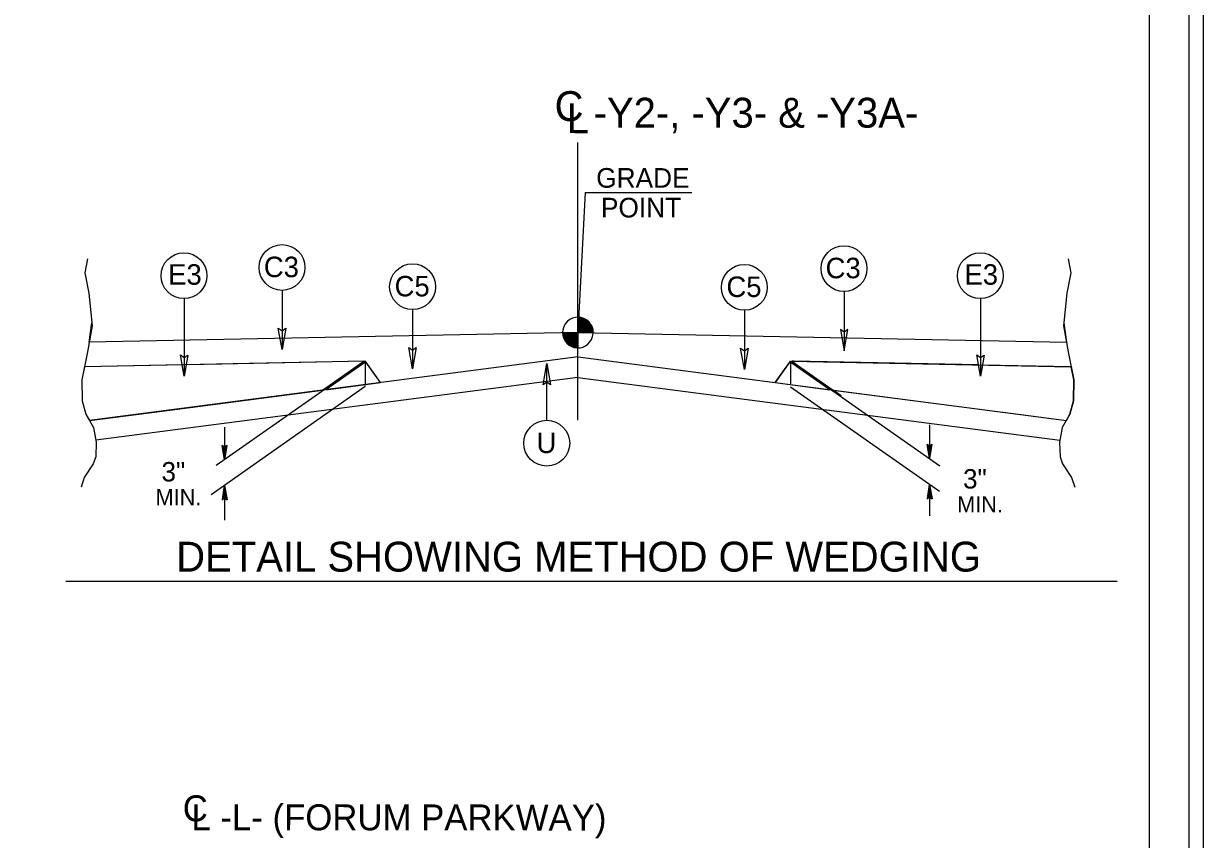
# Model space of a CAD drawing. Extents: x 1904401 to 1905163, y 193929 to 194736.
# Drawn here: x 1904973 to 1905047.5, y 194555.3 to 194606.9 of the extents above; entities that cross this region are included whole.
import ezdxf

# ---------------------------------------------------------------- set-up
doc = ezdxf.new("R2010")
doc.units = 0
for name, color, linetype in [('Old_Level_1', 7, 'Continuous'), ('Old_Level_11', 7, 'Continuous'), ('Old_Level_2', 7, 'Continuous'), ('Old_Level_20', 7, 'Continuous'), ('Old_Level_21', 7, 'Continuous'), ('Old_Level_3', 7, 'Continuous'), ('Prop Shade Medium', 7, 'Continuous'), ('Sheet Plot Border Inside CELL', 7, 'Continuous'), ('Sheet Plot Border Outside CELL', 7, 'Continuous'), ('Sheet Typical CELL', 7, 'Continuous'), ('Typical Text Centerline CELL', 7, 'Continuous')]:
    doc.layers.add(name, color=color, linetype=linetype)

msp = doc.modelspace()

# ---------------------------------------------------------------- linework, layer by layer
at = {"layer": 'Old_Level_1'}
for p, q in [((1905007.984, 194581.801), (1905007.984, 194599.347)), ((1905007.984, 194587.34), (1905007.984, 194588.305)), ((1905007.017, 194587.34), (1905007.984, 194587.34)), ((1905007.978, 194586.373), (1905007.978, 194587.329)), ((1905007.984, 194587.34), (1905007.984, 194586.373)), ((1905008.952, 194587.34), (1905007.984, 194587.34)), ((1905007.984, 194586.373), (1905007.984, 194587.34)), ((1904994.56, 194585.532), (1904976.825, 194585.177)), ((1904994.56, 194585.532), (1904985.144, 194578.938)), ((1904995.525, 194584.177), (1904994.56, 194585.532)), ((1904994.56, 194585.532), (1904994.56, 194583.985)), ((1905020.446, 194584.18), (1905021.408, 194585.532)), ((1905021.408, 194585.532), (1905039.145, 194585.177)), ((1905021.408, 194585.532), (1905021.408, 194584.094)), ((1905021.409, 194585.532), (1905030.84, 194578.928)), ((1904994.553, 194583.937), (1904984.818, 194577.085)), ((1905021.408, 194583.907), (1905030.824, 194577.311)), ((1904985.674, 194581.358), (1904985.674, 194579.307)), ((1905030.202, 194581.508), (1905030.202, 194579.375)), ((1904985.674, 194579.307), (1904985.513, 194580.21)), ((1904985.674, 194580.094), (1904985.513, 194580.21)), ((1904985.674, 194579.307), (1904985.536, 194580.194)), ((1904985.561, 194580.176), (1904985.674, 194579.307)), ((1904985.674, 194579.307), (1904985.584, 194580.16)), ((1904985.606, 194580.144), (1904985.674, 194579.307)), ((1904985.674, 194579.307), (1904985.628, 194580.128)), ((1904985.651, 194580.111), (1904985.674, 194579.307)), ((1904985.674, 194579.307), (1904985.833, 194580.21)), ((1904985.833, 194580.21), (1904985.674, 194580.094)), ((1904985.81, 194580.194), (1904985.674, 194579.307)), ((1904985.674, 194579.307), (1904985.788, 194580.176)), ((1904985.765, 194580.16), (1904985.674, 194579.307)), ((1904985.674, 194579.307), (1904985.741, 194580.144)), ((1904985.72, 194580.128), (1904985.674, 194579.307)), ((1904985.674, 194579.307), (1904985.697, 194580.111)), ((1904985.674, 194580.094), (1904985.674, 194579.307)), ((1905030.202, 194579.375), (1905030.043, 194580.277)), ((1905030.202, 194580.16), (1905030.043, 194580.277)), ((1905030.202, 194579.375), (1905030.066, 194580.26)), ((1905030.088, 194580.244), (1905030.202, 194579.375)), ((1905030.202, 194579.375), (1905030.11, 194580.228)), ((1905030.133, 194580.21), (1905030.202, 194579.375)), ((1905030.202, 194579.375), (1905030.156, 194580.194)), ((1905030.178, 194580.176), (1905030.202, 194579.375)), ((1905030.202, 194579.375), (1905030.36, 194580.277)), ((1905030.36, 194580.277), (1905030.202, 194580.16)), ((1905030.337, 194580.26), (1905030.202, 194579.375)), ((1905030.202, 194579.375), (1905030.315, 194580.244)), ((1905030.292, 194580.228), (1905030.202, 194579.375)), ((1905030.202, 194579.375), (1905030.269, 194580.21)), ((1905030.247, 194580.194), (1905030.202, 194579.375)), ((1905030.202, 194579.375), (1905030.224, 194580.176)), ((1905030.202, 194580.16), (1905030.202, 194579.375)), ((1904985.674, 194577.686), (1904985.513, 194576.783)), ((1904985.538, 194576.8), (1904985.674, 194577.686)), ((1904985.674, 194577.686), (1904985.561, 194576.817)), ((1904985.584, 194576.833), (1904985.674, 194577.686)), ((1904985.674, 194577.686), (1904985.606, 194576.85)), ((1904985.628, 194576.866), (1904985.674, 194577.686)), ((1904985.674, 194577.686), (1904985.651, 194576.883)), ((1904985.674, 194577.686), (1904985.674, 194575.492)), ((1904985.674, 194577.686), (1904985.833, 194576.783)), ((1904985.674, 194576.9), (1904985.674, 194577.686)), ((1904985.697, 194576.883), (1904985.674, 194577.686)), ((1904985.674, 194577.686), (1904985.72, 194576.866)), ((1904985.743, 194576.85), (1904985.674, 194577.686)), ((1904985.674, 194577.686), (1904985.765, 194576.833)), ((1904985.788, 194576.817), (1904985.674, 194577.686)), ((1904985.674, 194577.686), (1904985.81, 194576.8)), ((1905030.202, 194577.748), (1905030.043, 194576.846)), ((1905030.066, 194576.863), (1905030.202, 194577.748)), ((1905030.202, 194577.748), (1905030.088, 194576.88)), ((1905030.11, 194576.897), (1905030.202, 194577.748)), ((1905030.202, 194577.748), (1905030.133, 194576.914)), ((1905030.156, 194576.931), (1905030.202, 194577.748)), ((1905030.202, 194577.748), (1905030.178, 194576.946)), ((1905030.202, 194577.748), (1905030.202, 194575.768)), ((1905030.202, 194577.748), (1905030.36, 194576.846)), ((1905030.202, 194576.965), (1905030.202, 194577.748)), ((1905030.224, 194576.946), (1905030.202, 194577.748)), ((1905030.202, 194577.748), (1905030.247, 194576.931)), ((1905030.269, 194576.914), (1905030.202, 194577.748)), ((1905030.202, 194577.748), (1905030.292, 194576.897)), ((1905030.315, 194576.88), (1905030.202, 194577.748)), ((1905030.202, 194577.748), (1905030.337, 194576.863)), ((1904985.513, 194576.783), (1904985.674, 194576.9)), ((1904985.674, 194576.9), (1904985.833, 194576.783)), ((1905030.043, 194576.846), (1905030.202, 194576.965)), ((1905030.202, 194576.965), (1905030.36, 194576.846))]:
    msp.add_line(p, q, dxfattribs=at)
for points in [[(1904977.013, 194592.005), (1904976.85, 194591.106), (1904977.096, 194589.828), (1904977.312, 194587.76), (1904977.013, 194586.126), (1904976.66, 194584.357), (1904976.687, 194583.023), (1904976.905, 194582.18), (1904977.396, 194581.335), (1904977.558, 194580.41), (1904977.531, 194579.485), (1904977.368, 194579.048), (1904976.797, 194578.177), (1904976.606, 194577.578)], [(1905038.956, 194592.005), (1905039.119, 194591.106), (1905038.874, 194589.828), (1905038.657, 194587.76), (1905038.956, 194586.126), (1905039.31, 194584.357), (1905039.283, 194583.023), (1905039.064, 194582.18), (1905038.574, 194581.335), (1905038.412, 194580.41), (1905038.438, 194579.485), (1905038.602, 194579.048), (1905039.172, 194578.177), (1905039.363, 194577.578)], [(1905007.993, 194588.305), (1905007.993, 194588.305), (1905007.993, 194587.34)], [(1905008.012, 194588.305), (1905008.012, 194587.34)], [(1905008.032, 194588.305), (1905008.032, 194587.34)], [(1905008.051, 194588.304), (1905008.051, 194587.34)], [(1905008.072, 194588.303), (1905008.072, 194587.34)], [(1905008.09, 194588.3), (1905008.09, 194587.34)], [(1905008.11, 194588.299), (1905008.11, 194587.34)], [(1905008.128, 194588.295), (1905008.128, 194587.34)], [(1905008.148, 194588.292), (1905008.148, 194587.34)], [(1905008.167, 194588.288), (1905008.167, 194587.34)], [(1905008.187, 194588.286), (1905008.187, 194587.34)], [(1905008.207, 194588.281), (1905008.207, 194587.34)], [(1905008.226, 194588.276), (1905008.226, 194587.34)], [(1905008.245, 194588.27), (1905008.245, 194587.34)], [(1905008.263, 194588.265), (1905008.263, 194587.34)], [(1905008.282, 194588.259), (1905008.282, 194587.34)], [(1905008.303, 194588.252), (1905008.303, 194587.34)], [(1905008.322, 194588.246), (1905008.322, 194587.34)], [(1905008.342, 194588.238), (1905008.342, 194587.34)], [(1905008.362, 194588.23), (1905008.36, 194587.34)], [(1905008.381, 194588.221), (1905008.381, 194587.34)], [(1905008.399, 194588.213), (1905008.399, 194587.34)], [(1905008.418, 194588.204), (1905008.418, 194587.34)], [(1905008.438, 194588.193), (1905008.438, 194587.34)], [(1905008.457, 194588.181), (1905008.457, 194587.34)], [(1905008.477, 194588.17), (1905008.477, 194587.34)], [(1905008.497, 194588.159), (1905008.496, 194587.34)], [(1905008.516, 194588.148), (1905008.516, 194587.34)], [(1905008.534, 194588.134), (1905008.534, 194587.34)], [(1905008.553, 194588.12), (1905008.553, 194587.34)], [(1905008.574, 194588.106), (1905008.574, 194587.34)], [(1905008.593, 194588.091), (1905008.593, 194587.34)], [(1905008.613, 194588.074), (1905008.613, 194587.34)], [(1905008.632, 194588.058), (1905008.631, 194587.339)], [(1905008.652, 194588.039), (1905008.652, 194587.34)], [(1905008.669, 194588.021), (1905008.669, 194587.339)], [(1905008.689, 194588), (1905008.689, 194587.339)], [(1905008.709, 194587.978), (1905008.709, 194587.34)], [(1905008.728, 194587.956), (1905008.728, 194587.339)], [(1905008.749, 194587.932), (1905008.749, 194587.339)], [(1905008.768, 194587.907), (1905008.766, 194587.34)], [(1905008.786, 194587.88), (1905008.786, 194587.339)], [(1905008.804, 194587.849), (1905008.804, 194587.339)], [(1905007.022, 194587.34), (1905007.022, 194587.234)], [(1905007.042, 194587.34), (1905007.042, 194587.121)], [(1905007.062, 194587.34), (1905007.062, 194587.051)], [(1905007.082, 194587.34), (1905007.082, 194586.995)], [(1905007.099, 194587.34), (1905007.099, 194586.947)], [(1905007.119, 194587.34), (1905007.119, 194586.907)], [(1905007.137, 194587.34), (1905007.137, 194586.871)], [(1905007.158, 194587.34), (1905007.158, 194586.837)], [(1905007.177, 194587.34), (1905007.177, 194586.807)], [(1905007.197, 194587.34), (1905007.197, 194586.777)], [(1905007.217, 194587.34), (1905007.217, 194586.752)], [(1905007.235, 194587.34), (1905007.235, 194586.728)], [(1905007.254, 194587.34), (1905007.254, 194586.704)], [(1905007.273, 194587.34), (1905007.273, 194586.683)], [(1905007.293, 194587.34), (1905007.293, 194586.663)], [(1905007.312, 194587.34), (1905007.312, 194586.645)], [(1905007.333, 194587.34), (1905007.333, 194586.625)], [(1905007.352, 194587.34), (1905007.351, 194586.608)], [(1905007.37, 194587.34), (1905007.37, 194586.591)], [(1905007.389, 194587.34), (1905007.389, 194586.577)], [(1905007.409, 194587.34), (1905007.409, 194586.563)], [(1905007.429, 194587.34), (1905007.429, 194586.549)], [(1905007.448, 194587.34), (1905007.448, 194586.535)], [(1905007.468, 194587.34), (1905007.468, 194586.522)], [(1905007.487, 194587.34), (1905007.486, 194586.51)], [(1905007.506, 194587.34), (1905007.506, 194586.498)], [(1905007.524, 194587.34), (1905007.524, 194586.488)], [(1905007.544, 194587.34), (1905007.544, 194586.478)], [(1905007.564, 194587.34), (1905007.564, 194586.468)], [(1905007.583, 194587.34), (1905007.583, 194586.46)], [(1905007.604, 194587.34), (1905007.604, 194586.45)], [(1905007.623, 194587.34), (1905007.622, 194586.444)], [(1905007.641, 194587.34), (1905007.641, 194586.436)], [(1905007.661, 194587.34), (1905007.661, 194586.427)], [(1905007.679, 194587.34), (1905007.679, 194586.422)], [(1905007.699, 194587.34), (1905007.699, 194586.416)], [(1905007.719, 194587.34), (1905007.719, 194586.41)], [(1905007.738, 194587.34), (1905007.738, 194586.405)], [(1905007.758, 194587.34), (1905007.757, 194586.399)], [(1905007.776, 194587.34), (1905007.776, 194586.396)], [(1905007.797, 194587.34), (1905007.796, 194586.392)], [(1905007.814, 194587.34), (1905007.814, 194586.388)], [(1905007.835, 194587.34), (1905007.835, 194586.385)], [(1905007.854, 194587.34), (1905007.854, 194586.381)], [(1905007.875, 194587.34), (1905007.875, 194586.38)], [(1905007.893, 194587.34), (1905007.892, 194586.376)], [(1905007.911, 194587.34), (1905007.911, 194586.376)], [(1905007.932, 194587.34), (1905007.931, 194586.374)], [(1905007.95, 194587.34), (1905007.95, 194586.374)], [(1905007.97, 194587.34), (1905007.97, 194586.373), (1905007.97, 194586.373)], [(1905008.824, 194587.817), (1905008.824, 194587.34)], [(1905008.844, 194587.781), (1905008.844, 194587.339)], [(1905008.864, 194587.74), (1905008.864, 194587.339)], [(1905008.883, 194587.696), (1905008.883, 194587.34)], [(1905008.902, 194587.641), (1905008.902, 194587.339)], [(1905008.922, 194587.576), (1905008.922, 194587.339)], [(1905008.94, 194587.476), (1905008.94, 194587.34)]]:
    msp.add_lwpolyline(points, dxfattribs=at)
for start, end in [(358.00034, 356.17131), (359.99048, 89.99048), (179.99048, 268.71864), (269.65334, 269.99048)]:
    msp.add_arc((1905007.984, 194587.339), 0.967, start, end, dxfattribs=at)
at = {"layer": 'Old_Level_11'}
for p, q in [((1904983.121, 194589.486), (1904983.121, 194584.581)), ((1904989.302, 194590.006), (1904989.302, 194586.267)), ((1905024.795, 194589.935), (1905024.795, 194586.196)), ((1905033.413, 194589.486), (1905033.413, 194584.581)), ((1904997.544, 194588.789), (1904997.544, 194585.05)), ((1905018.502, 194588.751), (1905018.502, 194585.012)), ((1904977.124, 194586.723), (1904977.299, 194587.955)), ((1905038.671, 194587.955), (1905038.847, 194586.723)), ((1905007.984, 194587.339), (1904977.124, 194586.723)), ((1905007.984, 194587.34), (1905038.847, 194586.723)), ((1905007.996, 194585.8), (1904977.136, 194581.783)), ((1905007.996, 194585.8), (1905038.836, 194581.787)), ((1905006.021, 194581.797), (1905006.021, 194585.375)), ((1905007.986, 194584.497), (1904977.537, 194580.533)), ((1905007.986, 194584.497), (1905038.434, 194580.535)), ((1904975.657, 194571.626), (1905042.049, 194571.626))]:
    msp.add_line(p, q, dxfattribs=at)
for points in [[(1904989.533, 194587.607), (1904989.302, 194586.267), (1904989.064, 194587.614), (1904989.302, 194587.443)], [(1905024.564, 194587.536), (1905024.795, 194586.196), (1905025.033, 194587.543), (1905024.795, 194587.372)], [(1904997.775, 194586.389), (1904997.544, 194585.05), (1904997.306, 194586.397), (1904997.544, 194586.226)], [(1905018.733, 194586.351), (1905018.502, 194585.012), (1905018.264, 194586.359), (1905018.502, 194586.188)], [(1904983.351, 194585.921), (1904983.121, 194584.581), (1904982.883, 194585.928), (1904983.121, 194585.757)], [(1905033.643, 194585.921), (1905033.413, 194584.581), (1905033.175, 194585.928), (1905033.413, 194585.757)], [(1905005.79, 194584.036), (1905006.021, 194585.375), (1905006.26, 194584.029), (1905006.021, 194584.2)]]:
    msp.add_lwpolyline(points, close=True, dxfattribs=at)
for centre in [(1904983.106, 194590.933), (1904989.302, 194591.452), (1905024.795, 194591.382), (1905033.399, 194590.933), (1904997.545, 194590.235), (1905018.502, 194590.197), (1905006.021, 194580.35)]:
    msp.add_circle(centre, 1.447, dxfattribs=at)
at = {"layer": 'Old_Level_3'}
for p, q in [((1905008.453, 194596.192), (1905007.98, 194587.34)), ((1905008.452, 194596.192), (1905015.175, 194596.192))]:
    msp.add_line(p, q, dxfattribs=at)
at = {"layer": 'Prop Shade Medium'}
for p, q in [((1904976.825, 194585.177), (1904976.66, 194584.357)), ((1904982.994, 194585.301), (1904976.825, 194585.177)), ((1904994.474, 194585.53), (1904985.494, 194585.351)), ((1904991.859, 194583.699), (1904994.474, 194585.53)), ((1905021.601, 194585.531), (1905021.495, 194585.53)), ((1905021.495, 194585.53), (1905024.613, 194583.347)), ((1905033.287, 194585.294), (1905021.601, 194585.531)), ((1905039.145, 194585.177), (1905033.535, 194585.289)), ((1904981.724, 194582.38), (1904991.859, 194583.699)), ((1905024.613, 194583.347), (1905024.103, 194583.704)), ((1905024.103, 194583.704), (1905035.97, 194582.16)), ((1905024.613, 194583.347), (1905024.613, 194583.347)), ((1905024.613, 194583.347), (1905024.613, 194583.347)), ((1905024.613, 194583.347), (1905024.613, 194583.347)), ((1905024.613, 194583.347), (1905024.613, 194583.347)), ((1905024.613, 194583.347), (1905024.613, 194583.347)), ((1905035.97, 194582.16), (1905038.836, 194581.787)), ((1905035.97, 194582.16), (1905035.97, 194582.16))]:
    msp.add_line(p, q, dxfattribs=at)
for points in [[(1904985.494, 194585.351), (1904983.245, 194585.306), (1904983.121, 194584.581), (1904982.994, 194585.301)], [(1905033.535, 194585.289), (1905033.413, 194584.581), (1905033.287, 194585.294)], [(1905038.836, 194581.787), (1905039.064, 194582.18), (1905039.283, 194583.023), (1905039.31, 194584.357), (1905039.145, 194585.177)], [(1904976.66, 194584.357), (1904976.687, 194583.023), (1904976.905, 194582.18)], [(1904976.905, 194582.18), (1904977.136, 194581.783), (1904981.724, 194582.38)]]:
    msp.add_lwpolyline(points, dxfattribs=at)
for points in [[(1904995.525, 194584.177), (1904994.588, 194585.493), (1904992.065, 194583.726)], [(1905021.38, 194585.494), (1905020.446, 194584.18), (1905023.898, 194583.731)]]:
    msp.add_lwpolyline(points, close=True, dxfattribs=at)
at = {"layer": 'Sheet Plot Border Inside CELL'}
msp.add_lwpolyline([(1905046.592, 194709.705), (1904713.292, 194709.705), (1904713.292, 194498.685), (1905046.592, 194498.685)], close=True, dxfattribs=at)
at = {"layer": 'Sheet Plot Border Outside CELL'}
msp.add_lwpolyline([(1905047.492, 194714.195), (1904710.692, 194714.195), (1904710.692, 194494.195), (1905047.492, 194494.195)], close=True, dxfattribs=at)
at = {"layer": 'Sheet Typical CELL'}
msp.add_lwpolyline([(1905044.092, 194709.195), (1904744.092, 194709.195), (1904744.092, 194499.195), (1905044.092, 194499.195)], close=True, dxfattribs=at)

# ---------------------------------------------------------------- texts
at = {"layer": 'Old_Level_11'}
for s, p in [('GRADE', (1905009.144, 194596.491)), ('POINT', (1905009.443, 194594.612))]:
    msp.add_text(s, height=1.2398, dxfattribs=at).set_placement(p)
at = {"layer": 'Old_Level_2'}
msp.add_text('C', height=1.89, dxfattribs=at).set_placement((1905006.516, 194600.7))
msp.add_text('L', height=1.89, rotation=359.9469, dxfattribs=at).set_placement((1905007.276, 194599.937))
at = {"layer": 'Old_Level_20'}
for s, height, p in [('-Y2-, -Y3- & -Y3A-', 1.89, (1905008.981, 194600.283)), ('E3', 1.2949, (1904982.112, 194590.363)), ('C3', 1.2949, (1904988.154, 194590.841)), ('C3', 1.2949, (1905023.632, 194590.771)), ('E3', 1.2949, (1905032.405, 194590.363)), ('C5', 1.2949, (1904996.412, 194589.624)), ('C5', 1.2949, (1905017.37, 194589.586)), ('U', 1.295, (1905005.374, 194579.728)), ('3"', 1.2268, (1904981.69, 194577.933)), ('3"', 1.2268, (1905032.314, 194577.487))]:
    msp.add_text(s, height=height, dxfattribs=at).set_placement(p)
at = {"layer": 'Old_Level_21'}
for s, height, p in [('MIN.', 1.0252, (1904981.314, 194576.425)), ('MIN.', 1.0252, (1905031.938, 194575.979)), ('DETAIL SHOWING METHOD OF WEDGING', 1.89, (1904982.614, 194572.238))]:
    msp.add_text(s, height=height, dxfattribs=at).set_placement(p)
at = {"layer": 'Typical Text Centerline CELL'}
msp.add_text('C', height=1.64, dxfattribs=at).set_placement((1904983.031, 194556.463))
msp.add_text('L -L- (FORUM PARKWAY)', height=1.64109, rotation=359.9469, dxfattribs=at).set_placement((1904983.577, 194555.903))

doc.saveas('drawing.dxf')
